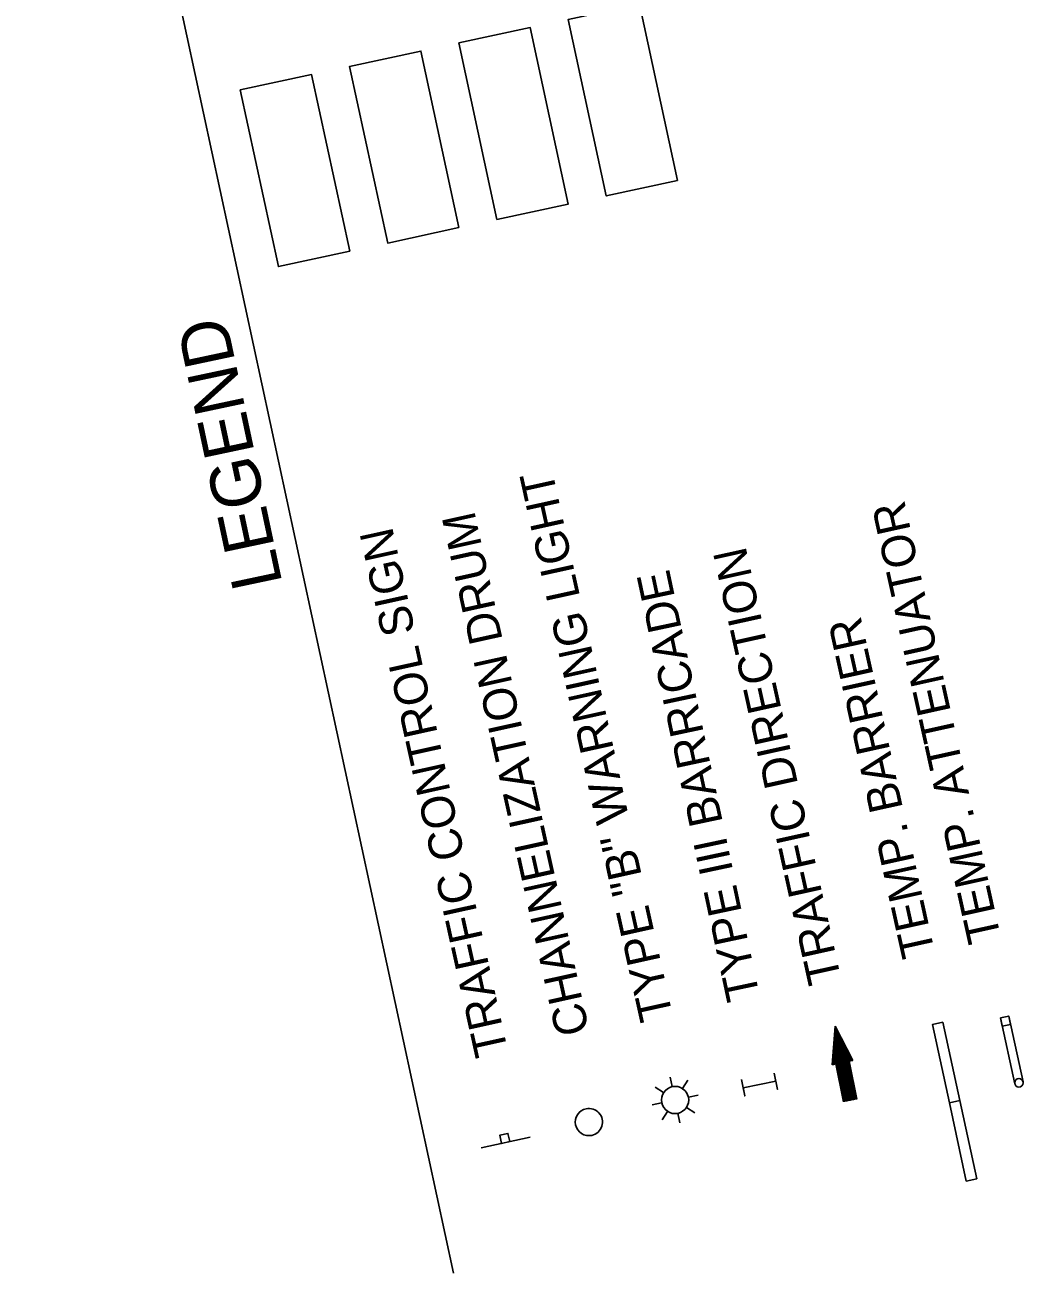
# Model space of a CAD drawing. Extents: x 1795987 to 1799700, y 243690 to 251545.
# Drawn here: x 1799466.6 to 1799700.4, y 250222 to 250514.1 of the extents above; entities that cross this region are included whole.
import ezdxf

# ---------------------------------------------------------------- set-up
doc = ezdxf.new("R2010")
doc.units = 0
for name, color, linetype in [('LEGEND', 7, 'Continuous'), ('Level 23', 7, 'Continuous'), ('Level 62', 7, 'Continuous')]:
    doc.layers.add(name, color=color, linetype=linetype)

# ---------------------------------------------------------------- blocks, each defined once
blk = doc.blocks.new('T21LR')
at = {"layer": 'Level 23'}
for p, q in [((0, 2), (31.5, 2)), ((0, -2), (31.5, -2))]:
    blk.add_line(p, q, dxfattribs=at)
blk.add_lwpolyline([(0, -2), (4, -2), (4, 2), (0, 2)], close=True, dxfattribs=at)
blk.add_circle((31.5, 0), 2, dxfattribs=at)

msp = doc.modelspace()

# ---------------------------------------------------------------- linework, layer by layer
at = {"layer": 'LEGEND'}
for p, q in [((1799566.87, 250222.02), (1799466.61, 250687.41)), ((1799656.18, 250279.76), (1799655.44, 250270.78)), ((1799660.34, 250271.77), (1799656.18, 250279.76)), ((1799655.44, 250270.78), (1799656.36, 250270.97)), ((1799656.36, 250270.97), (1799658.16, 250262.06)), ((1799659.42, 250271.58), (1799660.34, 250271.77)), ((1799661.22, 250262.68), (1799659.42, 250271.58)), ((1799618.03, 250265.65), (1799617.55, 250267.9)), ((1799616.02, 250264.26), (1799614.08, 250265.51)), ((1799621.69, 250267.15), (1799620.44, 250265.21)), ((1799621.83, 250263.2), (1799624.09, 250263.68)), ((1799615.58, 250261.85), (1799613.32, 250261.36)), ((1799615.72, 250257.9), (1799616.97, 250259.84)), ((1799619.38, 250259.4), (1799619.86, 250257.14)), ((1799623.33, 250259.54), (1799621.39, 250260.79)), ((1799584.79, 250253.8), (1799573.35, 250251.34))]:
    msp.add_line(p, q, dxfattribs=at)
for points in [[(1799619.32, 250477.73), (1799610.41, 250519.05), (1799593.73, 250515.46), (1799602.63, 250474.13)], [(1799593.74, 250472.22), (1799584.84, 250513.54), (1799568.15, 250509.95), (1799577.05, 250468.62)], [(1799568.16, 250466.71), (1799559.26, 250508.03), (1799542.57, 250504.44), (1799551.47, 250463.11)], [(1799542.58, 250461.2), (1799533.68, 250502.52), (1799516.99, 250498.93), (1799525.9, 250457.6)], [(1799681.4, 250280.73), (1799678.95, 250280.21), (1799682.9, 250261.88), (1799685.35, 250262.41)], [(1799685.35, 250262.41), (1799682.9, 250261.88), (1799686.85, 250243.55), (1799689.3, 250244.08)], [(1799578.11, 250252.36), (1799577.7, 250254.27), (1799579.61, 250254.68), (1799580.02, 250252.77)]]:
    msp.add_lwpolyline(points, close=True, dxfattribs=at)
for points in [[(1799655.92, 250276.61), (1799658.83, 250262.2)], [(1799656, 250277.54), (1799659.08, 250262.25)], [(1799656.07, 250278.48), (1799659.34, 250262.3)], [(1799656.15, 250279.41), (1799659.59, 250262.35)], [(1799656.45, 250279.24), (1799659.85, 250262.4)], [(1799656.88, 250278.41), (1799660.1, 250262.46)], [(1799657.32, 250277.58), (1799660.36, 250262.51)], [(1799657.75, 250276.75), (1799660.61, 250262.56)], [(1799655.69, 250273.81), (1799656.27, 250270.95)], [(1799655.77, 250274.74), (1799658.32, 250262.1)], [(1799655.84, 250275.68), (1799658.57, 250262.15)], [(1799658.18, 250275.92), (1799660.87, 250262.61)], [(1799658.61, 250275.09), (1799661.12, 250262.66)], [(1799659.05, 250274.26), (1799659.58, 250271.61)], [(1799655.46, 250271.01), (1799655.5, 250270.79)], [(1799655.53, 250271.95), (1799655.76, 250270.84)], [(1799655.61, 250272.88), (1799656.01, 250270.9)], [(1799659.48, 250273.43), (1799659.83, 250271.67)], [(1799659.91, 250272.6), (1799660.09, 250271.72)], [(1799641.91, 250268.81), (1799642.67, 250264.98), (1799642.29, 250266.89), (1799634.64, 250265.38), (1799635.02, 250263.46), (1799634.26, 250267.29)]]:
    msp.add_lwpolyline(points, dxfattribs=at)
msp.add_circle((1799618.71, 250262.52), 3.19, dxfattribs=at)
for start, end in [(102.1577, 282.1577), (282.1577, 102.1577)]:
    msp.add_arc((1799598.56, 250257.35), 3.18, start, end, dxfattribs=at)
at = {"layer": 'Level 62'}
msp.add_lwpolyline([(1799577.05, 250468.62), (1799593.74, 250472.22), (1799584.84, 250513.54), (1799568.15, 250509.95), (1799577.05, 250468.62)], dxfattribs=at)

# ---------------------------------------------------------------- block references
at = {"layer": 'LEGEND', "xscale": 0.5000000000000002, "yscale": 0.5000000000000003, "rotation": -77.69303510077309}
msp.add_blockref('T21LR', (1799695.82, 250281.94), dxfattribs=at)

# ---------------------------------------------------------------- texts
at = {"layer": 'LEGEND'}
for s, height, rotation, p in [('LEGEND', 11.7, 101.9916, (1799526.88, 250383.46)), ('TYPE "B" WARNING LIGHT', 7.7999, 102.4707, (1799618.28, 250281.94)), ('TEMP. ATTENUATOR', 7.7999, 102.4707, (1799695.06, 250300.2)), ('CHANNELIZATION DRUM', 7.7999, 102.4707, (1799598.71, 250278.49)), ('TRAFFIC CONTROL SIGN', 7.7999, 102.4707, (1799579.72, 250273.64)), ('TRAFFIC DIRECTION', 7.7999, 102.4707, (1799657.67, 250290.57)), ('TYPE III BARRICADE', 7.7999, 101.9916, (1799638.6, 250286.63)), ('TEMP. BARRIER', 7.7999, 102.4707, (1799679.59, 250296.81))]:
    msp.add_text(s, height=height, rotation=rotation, dxfattribs=at).set_placement(p)

doc.saveas('drawing.dxf')
